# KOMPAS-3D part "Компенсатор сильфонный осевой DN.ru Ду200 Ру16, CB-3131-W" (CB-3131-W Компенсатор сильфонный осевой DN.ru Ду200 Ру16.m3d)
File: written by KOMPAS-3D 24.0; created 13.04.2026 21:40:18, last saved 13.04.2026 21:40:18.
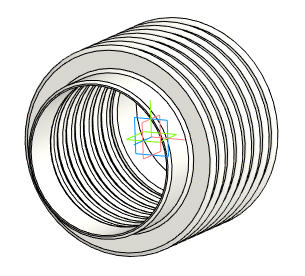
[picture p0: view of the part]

Document properties: Автор: DN.RU; Полное имя файла: D:\PROJECT CAD\DN.RU\...197(ACTUALE). CB-3131-W Компенсатор сильфонный осевой DN.ru\Исходники\DN200\CB-3131-W Компенсатор сильфонный осевой DN.ru Ду200 Ру16.m3d

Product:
- Body: Твердое тело1  | qty 1
    Масса: 17.044776
- Part/product: Компенсатор сильфонный осевой DN.ru Ду200 Ру16  | designation CB-3131-W
    Масса: 9.2
    Раздел спецификации: Прочие изделия
    Комментарий: D140-02127
    Примечание: D140-02127
    additional columns: Типовые

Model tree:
1. Твердое тело1  (labels: Твердое тело1)

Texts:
  CB-3131-W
